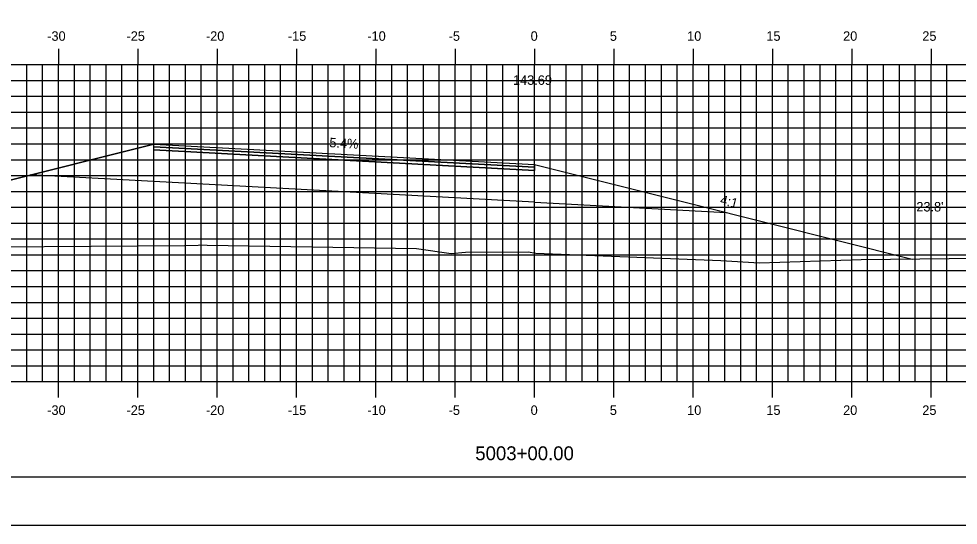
# Model space of a CAD drawing. Extents: x 851639 to 851810, y 365876 to 365986.
# Drawn here: x 851689.2 to 851748.4, y 365875.8 to 365907.7 of the extents above; entities that cross this region are included whole.
import ezdxf

# ---------------------------------------------------------------- set-up
doc = ezdxf.new("R2010")
doc.units = 0
for name, color, linetype in [('ANNOTATION', 7, 'Continuous'), ('BORDER', 7, 'Continuous'), ('D_Roadway_Centerline', 7, 'Continuous'), ('D_Roadway_Centerline_Text', 7, 'Continuous'), ('D_Roadway_Edge_TW', 7, 'Continuous'), ('D_Roadway_FinishedGrade', 7, 'Continuous'), ('D_Roadway_Pavement', 7, 'Continuous'), ('D_Roadway_SlopeLines', 7, 'Continuous'), ('D_Roadway_SubGrade', 7, 'Continuous'), ('D_Text_Standard', 7, 'Continuous'), ('H_V ANNOTATION', 7, 'Continuous'), ('MAJOR', 7, 'Continuous'), ('MINOR', 7, 'Continuous'), ('PLOT BOUNDARY', 7, 'Continuous'), ('S_Roadway_Centerline', 7, 'Continuous')]:
    doc.layers.add(name, color=color, linetype=linetype)

msp = doc.modelspace()

# ---------------------------------------------------------------- linework, layer by layer
at = {"layer": 'BORDER'}
msp.add_lwpolyline([(851646.655, 365878.833), (851806.655, 365878.833), (851806.655, 365983.833), (851646.655, 365983.833)], close=True, dxfattribs=at)
at = {"layer": 'D_Roadway_Centerline'}
msp.add_lwpolyline([(851671.874, 365893.373), (851687.655, 365897.318), (851697.655, 365899.818), (851721.655, 365898.522), (851731.655, 365896.022), (851745.471, 365892.568)], dxfattribs=at)
at = {"layer": 'D_Roadway_Edge_TW'}
msp.add_lwpolyline([(851697.655, 365899.818), (851721.655, 365898.522), (851721.655, 365898.355), (851697.655, 365899.651)], close=True, dxfattribs=at)
at = {"layer": 'D_Roadway_FinishedGrade'}
for p, q in [((851697.655, 365897.451), (851689.87, 365897.872)), ((851721.655, 365896.155), (851733.73, 365895.503))]:
    msp.add_line(p, q, dxfattribs=at)
at = {"layer": 'D_Roadway_Pavement'}
msp.add_lwpolyline([(851697.655, 365899.651), (851721.655, 365898.355), (851721.655, 365898.155), (851697.655, 365899.451)], close=True, dxfattribs=at)
msp.add_lwpolyline([(851721.655, 365898.355), (851721.655, 365898.155)], dxfattribs=at)
msp.add_lwpolyline([(851721.655, 365898.355), (851721.655, 365898.155)], dxfattribs=at)
at = {"layer": 'D_Roadway_SlopeLines'}
for points in [[(851697.655, 365899.818), (851687.655, 365897.318), (851671.874, 365893.373)], [(851721.655, 365898.522), (851731.655, 365896.022), (851745.471, 365892.568)]]:
    msp.add_lwpolyline(points, dxfattribs=at)
at = {"layer": 'D_Roadway_SubGrade'}
for points in [[(851697.655, 365899.451), (851721.655, 365898.155)], [(851721.655, 365896.155), (851697.655, 365897.451)]]:
    msp.add_lwpolyline(points, dxfattribs=at)
at = {"layer": 'MAJOR'}
for p, q in [((851691.655, 365905.835), (851691.655, 365904.833)), ((851696.655, 365905.835), (851696.655, 365904.833)), ((851701.655, 365905.835), (851701.655, 365904.833)), ((851706.655, 365905.835), (851706.655, 365904.833)), ((851711.655, 365905.835), (851711.655, 365904.833)), ((851716.655, 365905.835), (851716.655, 365904.833)), ((851721.655, 365905.835), (851721.655, 365904.833)), ((851726.655, 365905.835), (851726.655, 365904.833)), ((851731.655, 365905.835), (851731.655, 365904.833)), ((851736.655, 365905.835), (851736.655, 365904.833)), ((851741.655, 365905.835), (851741.655, 365904.833)), ((851746.655, 365905.835), (851746.655, 365904.833)), ((851651.655, 365904.833), (851791.655, 365904.833)), ((851651.655, 365904.833), (851791.655, 365904.833)), ((851691.655, 365884.833), (851691.655, 365904.833)), ((851696.655, 365884.833), (851696.655, 365904.833)), ((851701.655, 365884.833), (851701.655, 365904.833)), ((851706.655, 365884.833), (851706.655, 365904.833)), ((851711.655, 365884.833), (851711.655, 365904.833)), ((851716.655, 365884.833), (851716.655, 365904.833)), ((851721.655, 365884.833), (851721.655, 365904.833)), ((851726.655, 365884.833), (851726.655, 365904.833)), ((851731.655, 365884.833), (851731.655, 365904.833)), ((851736.655, 365884.833), (851736.655, 365904.833)), ((851741.655, 365884.833), (851741.655, 365904.833)), ((851746.655, 365884.833), (851746.655, 365904.833)), ((851651.655, 365899.833), (851791.655, 365899.833)), ((851651.655, 365894.833), (851791.655, 365894.833)), ((851651.655, 365889.833), (851791.655, 365889.833)), ((851651.655, 365884.833), (851791.655, 365884.833)), ((851651.655, 365884.833), (851791.655, 365884.833)), ((851691.655, 365883.831), (851691.655, 365884.833)), ((851696.655, 365883.831), (851696.655, 365884.833)), ((851701.655, 365883.831), (851701.655, 365884.833)), ((851706.655, 365883.831), (851706.655, 365884.833)), ((851711.655, 365883.831), (851711.655, 365884.833)), ((851716.655, 365883.831), (851716.655, 365884.833)), ((851721.655, 365883.831), (851721.655, 365884.833)), ((851726.655, 365883.831), (851726.655, 365884.833)), ((851731.655, 365883.831), (851731.655, 365884.833)), ((851736.655, 365883.831), (851736.655, 365884.833)), ((851741.655, 365883.831), (851741.655, 365884.833)), ((851746.655, 365883.831), (851746.655, 365884.833))]:
    msp.add_line(p, q, dxfattribs=at)
at = {"layer": 'MINOR'}
for p, q in [((851689.655, 365884.833), (851689.655, 365904.833)), ((851690.655, 365884.833), (851690.655, 365904.833)), ((851692.655, 365884.833), (851692.655, 365904.833)), ((851693.655, 365884.833), (851693.655, 365904.833)), ((851694.655, 365884.833), (851694.655, 365904.833)), ((851695.655, 365884.833), (851695.655, 365904.833)), ((851697.655, 365884.833), (851697.655, 365904.833)), ((851698.655, 365884.833), (851698.655, 365904.833)), ((851699.655, 365884.833), (851699.655, 365904.833)), ((851700.655, 365884.833), (851700.655, 365904.833)), ((851702.655, 365884.833), (851702.655, 365904.833)), ((851703.655, 365884.833), (851703.655, 365904.833)), ((851704.655, 365884.833), (851704.655, 365904.833)), ((851705.655, 365884.833), (851705.655, 365904.833)), ((851707.655, 365884.833), (851707.655, 365904.833)), ((851708.655, 365884.833), (851708.655, 365904.833)), ((851709.655, 365884.833), (851709.655, 365904.833)), ((851710.655, 365884.833), (851710.655, 365904.833)), ((851712.655, 365884.833), (851712.655, 365904.833)), ((851713.655, 365884.833), (851713.655, 365904.833)), ((851714.655, 365884.833), (851714.655, 365904.833)), ((851715.655, 365884.833), (851715.655, 365904.833)), ((851717.655, 365884.833), (851717.655, 365904.833)), ((851718.655, 365884.833), (851718.655, 365904.833)), ((851719.655, 365884.833), (851719.655, 365904.833)), ((851720.655, 365884.833), (851720.655, 365904.833)), ((851722.655, 365884.833), (851722.655, 365904.833)), ((851723.655, 365884.833), (851723.655, 365904.833)), ((851724.655, 365884.833), (851724.655, 365904.833)), ((851725.655, 365884.833), (851725.655, 365904.833)), ((851727.655, 365884.833), (851727.655, 365904.833)), ((851728.655, 365884.833), (851728.655, 365904.833)), ((851729.655, 365884.833), (851729.655, 365904.833)), ((851730.655, 365884.833), (851730.655, 365904.833)), ((851732.655, 365884.833), (851732.655, 365904.833)), ((851733.655, 365884.833), (851733.655, 365904.833)), ((851734.655, 365884.833), (851734.655, 365904.833)), ((851735.655, 365884.833), (851735.655, 365904.833)), ((851737.655, 365884.833), (851737.655, 365904.833)), ((851738.655, 365884.833), (851738.655, 365904.833)), ((851739.655, 365884.833), (851739.655, 365904.833)), ((851740.655, 365884.833), (851740.655, 365904.833)), ((851742.655, 365884.833), (851742.655, 365904.833)), ((851743.655, 365884.833), (851743.655, 365904.833)), ((851744.655, 365884.833), (851744.655, 365904.833)), ((851745.655, 365884.833), (851745.655, 365904.833)), ((851747.655, 365884.833), (851747.655, 365904.833)), ((851651.655, 365903.833), (851791.655, 365903.833)), ((851651.655, 365902.833), (851791.655, 365902.833)), ((851651.655, 365901.833), (851791.655, 365901.833)), ((851651.655, 365900.833), (851791.655, 365900.833)), ((851651.655, 365898.833), (851791.655, 365898.833)), ((851651.655, 365897.833), (851791.655, 365897.833)), ((851651.655, 365896.833), (851791.655, 365896.833)), ((851651.655, 365895.833), (851791.655, 365895.833)), ((851651.655, 365893.833), (851791.655, 365893.833)), ((851651.655, 365892.833), (851791.655, 365892.833)), ((851651.655, 365891.833), (851791.655, 365891.833)), ((851651.655, 365890.833), (851791.655, 365890.833)), ((851651.655, 365888.833), (851791.655, 365888.833)), ((851651.655, 365887.833), (851791.655, 365887.833)), ((851651.655, 365886.833), (851791.655, 365886.833)), ((851651.655, 365885.833), (851791.655, 365885.833))]:
    msp.add_line(p, q, dxfattribs=at)
at = {"layer": 'PLOT BOUNDARY'}
msp.add_lwpolyline([(851638.562, 365875.774), (851808.562, 365875.774), (851808.562, 365985.774), (851638.562, 365985.774)], close=True, dxfattribs=at)
at = {"layer": 'S_Roadway_Centerline'}
msp.add_lwpolyline([(851651.655, 365892.733), (851662.235, 365893.118), (851663.147, 365893.17), (851665.705, 365893.279), (851669.359, 365893.281), (851673.643, 365893.437), (851673.705, 365893.453), (851678.861, 365893.43), (851681.907, 365893.287), (851699.598, 365893.427), (851700.467, 365893.433), (851700.542, 365893.452), (851701.031, 365893.434), (851714.216, 365893.233), (851716.404, 365892.925), (851717.299, 365893.001), (851721.258, 365893.02), (851721.746, 365892.928), (851733.393, 365892.465), (851735.836, 365892.322), (851742.245, 365892.534), (851749.65, 365892.612)], dxfattribs=at)

# ---------------------------------------------------------------- texts
at = {"layer": 'ANNOTATION'}
for s, rotation, p in [('5.4%', 356.90903, (851708.715, 365899.622)), ('4:1', 345.96376, (851733.316, 365896.038))]:
    msp.add_text(s, height=0.6, rotation=rotation, dxfattribs=at).set_placement(p)
at = {"layer": 'D_Roadway_Centerline_Text'}
msp.add_text('143.69', height=0.6, dxfattribs=at).set_placement((851720.301, 365903.554))
at = {"layer": 'D_Text_Standard'}
msp.add_text("23.8'", height=0.6, dxfattribs=at).set_placement((851745.725, 365895.565))
at = {"layer": 'H_V ANNOTATION'}
for s, height, p in [('-30', 0.6, (851690.943, 365906.333)), ('-25', 0.6, (851695.94, 365906.333)), ('-20', 0.6, (851700.948, 365906.333)), ('-15', 0.6, (851706.112, 365906.333)), ('-10', 0.6, (851711.12, 365906.333)), ('-5', 0.6, (851716.246, 365906.333)), ('0', 0.6, (851721.414, 365906.333)), ('5', 0.6, (851726.406, 365906.333)), ('10', 0.6, (851731.28, 365906.333)), ('15', 0.6, (851736.272, 365906.333)), ('20', 0.6, (851741.109, 365906.333)), ('25', 0.6, (851746.101, 365906.333)), ('-30', 0.6, (851690.943, 365882.733)), ('-25', 0.6, (851695.94, 365882.733)), ('-20', 0.6, (851700.948, 365882.733)), ('-15', 0.6, (851706.112, 365882.733)), ('-10', 0.6, (851711.12, 365882.733)), ('-5', 0.6, (851716.246, 365882.733)), ('0', 0.6, (851721.414, 365882.733)), ('5', 0.6, (851726.406, 365882.733)), ('10', 0.6, (851731.28, 365882.733)), ('15', 0.6, (851736.272, 365882.733)), ('20', 0.6, (851741.109, 365882.733)), ('25', 0.6, (851746.101, 365882.733)), ('5003+00.00', 0.875, (851717.925, 365879.876))]:
    msp.add_text(s, height=height, dxfattribs=at).set_placement(p)

doc.saveas('drawing.dxf')
